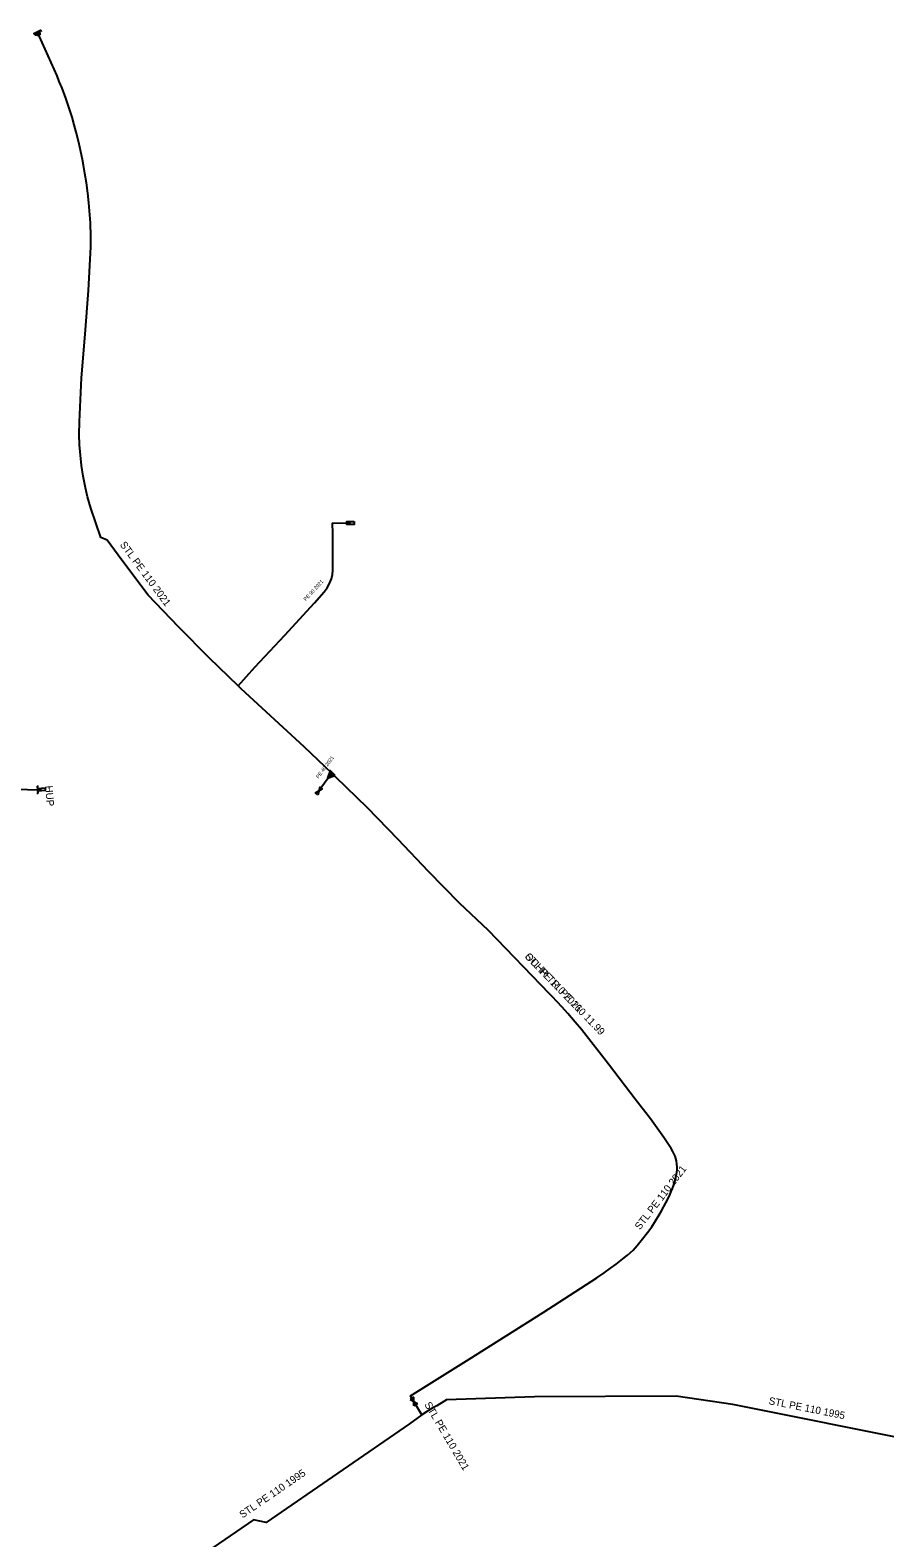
# Model space of a CAD drawing. Extents: x -734239 to -733693, y -1053757 to -1053379.
# Drawn here: x -734046.3 to -733929.8, y -1053596.5 to -1053391 of the extents above; entities that cross this region are included whole.
import ezdxf

# ---------------------------------------------------------------- set-up
doc = ezdxf.new("R2010")
doc.units = 0
for name, color, linetype in [('ST OP Chráni_ka - provoz', 7, 'Continuous'), ('ST Úsek p_ípojky - provoz', 7, 'Continuous'), ('ST Úsek plynovodu - provoz', 7, 'Continuous'), ('ST_HUP_22_23_popis', 7, 'Continuous'), ('Vrstva 1', 7, 'Continuous')]:
    doc.layers.add(name, color=color, linetype=linetype)

msp = doc.modelspace()

# ---------------------------------------------------------------- linework, layer by layer
at = {"layer": 'ST OP Chráni_ka - provoz'}
msp.add_lwpolyline([(-733975.51, -1053522.36), (-733983.84, -1053513.74)], dxfattribs=at)
at = {"layer": 'ST Úsek p_ípojky - provoz'}
for points in [[(-734017.98, -1053480.39), (-734015.69, -1053477.85), (-734011.61, -1053473.47), (-734007.56, -1053469.04), (-734006.24, -1053467.55), (-734005.83, -1053467.01), (-734005.5, -1053466.42), (-734005.26, -1053465.8), (-734005.11, -1053465.21), (-734005.04, -1053464.62), (-734005.04, -1053463.86), (-734005.08, -1053459.55), (-734005.09, -1053458.19), (-734002.93, -1053458.17), (-734002.65, -1053458.17)], [(-734005.43, -1053492.61), (-734006.98, -1053494.7)], [(-734005.16, -1053492.33), (-734005.43, -1053492.61)], [(-734056.77, -1053494.13), (-734056.37, -1053494.18), (-734045.32, -1053494.56)], [(-734045.32, -1053494.56), (-734044.78, -1053494.52)]]:
    msp.add_lwpolyline(points, dxfattribs=at)
at = {"layer": 'ST Úsek plynovodu - provoz'}
for points in [[(-733983.84, -1053513.74), (-733987.8, -1053509.99), (-733992, -1053505.69), (-733996.14, -1053501.33), (-734000.34, -1053497.03), (-734004.64, -1053492.85), (-734005.16, -1053492.33), (-734008.96, -1053488.69), (-734017.57, -1053480.78), (-734017.98, -1053480.39), (-734021.89, -1053476.62), (-734026.08, -1053472.34), (-734030.24, -1053468.01), (-734033.85, -1053463.23), (-734035.84, -1053460.54), (-734036.7, -1053460.16), (-734038.05, -1053456.17), (-734038.49, -1053454.59), (-734038.78, -1053453.4), (-734039.09, -1053451.81), (-734039.32, -1053450.33), (-734039.48, -1053448.95), (-734039.58, -1053447.5), (-734039.63, -1053446.1), (-734039.62, -1053444.37), (-734039.32, -1053438.39), (-734038.84, -1053432.43), (-734038.39, -1053426.48), (-734038.05, -1053420.51), (-734038.06, -1053419.11), (-734038.12, -1053417.26), (-734038.22, -1053415.61), (-734038.32, -1053414.52), (-734038.46, -1053413.22), (-734038.65, -1053411.82), (-734038.85, -1053410.54), (-734039.06, -1053409.41), (-734039.21, -1053408.63), (-734039.41, -1053407.59), (-734039.69, -1053406.31), (-734040.05, -1053404.87), (-734040.32, -1053403.88), (-734040.62, -1053402.83), (-734040.96, -1053401.76), (-734041.47, -1053400.24), (-734041.98, -1053398.88), (-734042.35, -1053397.97), (-734042.66, -1053397.22), (-734045.1, -1053391.76), (-734045.24, -1053391.46), (-734045.37, -1053391.2)], [(-733975.51, -1053522.36), (-733983.84, -1053513.74)], [(-733994.02, -1053577.94), (-733994.48, -1053577.19), (-733986.47, -1053572.19), (-733976.38, -1053565.81), (-733969.07, -1053561.09), (-733968.07, -1053560.42), (-733967.19, -1053559.79), (-733966.44, -1053559.23), (-733965.54, -1053558.52), (-733964.89, -1053557.98), (-733964.12, -1053557.31), (-733963.55, -1053556.67), (-733962.82, -1053555.79), (-733962.14, -1053554.9), (-733961.58, -1053554.12), (-733961.05, -1053553.31), (-733960.55, -1053552.51), (-733960.24, -1053551.97), (-733959.65, -1053550.87), (-733959.15, -1053549.93), (-733958.91, -1053549.34), (-733958.75, -1053548.92), (-733958.58, -1053548.41), (-733958.36, -1053547.64), (-733958.24, -1053547.15), (-733958.15, -1053546.7), (-733958.12, -1053546.37), (-733958.12, -1053545.99), (-733958.15, -1053545.58), (-733958.21, -1053545.16), (-733958.29, -1053544.84), (-733958.39, -1053544.52), (-733958.5, -1053544.24), (-733958.68, -1053543.86), (-733958.92, -1053543.46), (-733959.95, -1053541.94), (-733961.76, -1053539.4), (-733963.84, -1053536.74), (-733967.48, -1053531.98), (-733971.17, -1053527.25), (-733972.01, -1053526.22), (-733973, -1053525.06), (-733973.79, -1053524.18), (-733975.15, -1053522.75), (-733975.51, -1053522.36)], [(-733992.91, -1053579.78), (-733993.08, -1053579.54), (-733994.02, -1053577.94)], [(-733902.26, -1053596.38), (-733909.04, -1053590.79), (-733916.55, -1053586.18), (-733924.88, -1053583.48), (-733950.53, -1053578.36), (-733958.24, -1053577.23), (-733977.56, -1053577.32), (-733989.55, -1053577.74), (-733990.87, -1053578.54), (-733991.41, -1053578.81), (-733992.01, -1053579.18), (-733992.91, -1053579.78)], [(-733992.91, -1053579.78), (-733994.62, -1053581), (-734014.15, -1053594.44), (-734015.86, -1053594.09), (-734040.47, -1053610.96)]]:
    msp.add_lwpolyline(points, dxfattribs=at)
at = {"layer": 'Vrstva 1'}
for p, q in [((-734045.69, -1053391.68), (-734045.24, -1053391.46)), ((-734045.36, -1053494.06), (-734045.21, -1053494.05)), ((-734045.36, -1053494.06), (-734045.28, -1053495.06)), ((-734045.28, -1053495.06), (-734045.43, -1053495.07)), ((-733994.02, -1053577.36), (-733994.53, -1053577.67)), ((-733994.53, -1053577.67), (-733993.51, -1053578.22)), ((-733994.02, -1053578.53), (-733994.02, -1053577.36)), ((-733993.51, -1053578.22), (-733994.02, -1053578.53))]:
    msp.add_line(p, q, dxfattribs=at)
for points in [[(-734045.71, -1053391.64), (-734045.82, -1053391.42), (-734044.92, -1053390.98), (-734044.81, -1053391.21)], [(-734007.12, -1053495.22), (-734007.44, -1053494.98), (-734006.52, -1053494.42), (-734006.84, -1053494.18), (-734007.12, -1053495.22)]]:
    msp.add_lwpolyline(points, dxfattribs=at)
for points in [[(-734045.46, -1053391.58), (-734045.47, -1053391.56), (-734045.48, -1053391.54), (-734045.49, -1053391.51), (-734045.49, -1053391.49), (-734045.49, -1053391.46), (-734045.49, -1053391.44), (-734045.49, -1053391.41), (-734045.48, -1053391.39), (-734045.47, -1053391.37), (-734045.46, -1053391.35), (-734045.45, -1053391.32), (-734045.44, -1053391.3), (-734045.42, -1053391.29), (-734045.4, -1053391.27), (-734045.38, -1053391.26), (-734045.36, -1053391.24), (-734045.34, -1053391.23), (-734045.32, -1053391.22), (-734045.29, -1053391.22), (-734045.27, -1053391.21), (-734045.24, -1053391.21), (-734045.22, -1053391.21), (-734045.2, -1053391.22), (-734045.17, -1053391.22), (-734045.15, -1053391.23), (-734045.13, -1053391.24), (-734045.1, -1053391.25), (-734045.09, -1053391.27), (-734045.07, -1053391.28), (-734045.05, -1053391.3), (-734045.04, -1053391.32), (-734045.02, -1053391.34), (-734045.01, -1053391.36), (-734045, -1053391.39), (-734045, -1053391.41), (-734044.99, -1053391.44), (-734044.99, -1053391.46), (-734044.99, -1053391.49), (-734045, -1053391.51), (-734045, -1053391.53), (-734045.01, -1053391.56), (-734045.02, -1053391.58), (-734045.03, -1053391.6), (-734045.05, -1053391.62), (-734045.06, -1053391.64), (-734045.08, -1053391.65), (-734045.1, -1053391.67), (-734045.12, -1053391.68), (-734045.15, -1053391.69), (-734045.17, -1053391.7), (-734045.19, -1053391.71), (-734045.22, -1053391.71), (-734045.24, -1053391.71), (-734045.27, -1053391.71), (-734045.29, -1053391.71), (-734045.31, -1053391.7), (-734045.34, -1053391.69), (-734045.36, -1053391.68), (-734045.38, -1053391.67), (-734045.4, -1053391.66), (-734045.42, -1053391.64), (-734045.44, -1053391.62), (-734045.45, -1053391.6)], [(-734045.16, -1053391.62), (-734045.17, -1053391.62), (-734045.19, -1053391.63), (-734045.21, -1053391.63), (-734045.22, -1053391.64), (-734045.24, -1053391.64), (-734045.26, -1053391.64), (-734045.28, -1053391.63), (-734045.29, -1053391.63), (-734045.31, -1053391.62), (-734045.32, -1053391.62), (-734045.34, -1053391.61), (-734045.35, -1053391.6), (-734045.37, -1053391.59), (-734045.38, -1053391.57), (-734045.39, -1053391.56), (-734045.4, -1053391.55), (-734045.4, -1053391.53), (-734045.41, -1053391.51), (-734045.41, -1053391.5), (-734045.42, -1053391.48), (-734045.42, -1053391.46), (-734045.42, -1053391.45), (-734045.42, -1053391.43), (-734045.41, -1053391.41), (-734045.4, -1053391.4), (-734045.4, -1053391.38), (-734045.39, -1053391.37), (-734045.38, -1053391.35), (-734045.37, -1053391.34), (-734045.35, -1053391.33), (-734045.34, -1053391.32), (-734045.33, -1053391.31), (-734045.31, -1053391.3), (-734045.29, -1053391.29), (-734045.28, -1053391.29), (-734045.26, -1053391.29), (-734045.24, -1053391.29), (-734045.23, -1053391.29), (-734045.21, -1053391.29), (-734045.19, -1053391.29), (-734045.18, -1053391.3), (-734045.16, -1053391.31), (-734045.15, -1053391.32), (-734045.13, -1053391.33), (-734045.12, -1053391.34), (-734045.11, -1053391.35), (-734045.1, -1053391.36), (-734045.09, -1053391.38), (-734045.08, -1053391.39), (-734045.08, -1053391.41), (-734045.07, -1053391.43), (-734045.07, -1053391.44), (-734045.07, -1053391.46), (-734045.07, -1053391.48), (-734045.07, -1053391.5), (-734045.07, -1053391.51), (-734045.08, -1053391.53), (-734045.09, -1053391.54), (-734045.1, -1053391.56), (-734045.11, -1053391.57), (-734045.12, -1053391.59), (-734045.13, -1053391.6), (-734045.14, -1053391.61)], [(-734045.31, -1053391.33), (-734045.3, -1053391.32), (-734045.29, -1053391.32), (-734045.27, -1053391.31), (-734045.26, -1053391.31), (-734045.24, -1053391.31), (-734045.23, -1053391.31), (-734045.21, -1053391.31), (-734045.2, -1053391.32), (-734045.19, -1053391.32), (-734045.17, -1053391.33), (-734045.16, -1053391.34), (-734045.15, -1053391.35), (-734045.14, -1053391.36), (-734045.13, -1053391.37), (-734045.12, -1053391.38), (-734045.11, -1053391.39), (-734045.1, -1053391.4), (-734045.1, -1053391.42), (-734045.1, -1053391.43), (-734045.09, -1053391.45), (-734045.09, -1053391.46), (-734045.09, -1053391.48), (-734045.09, -1053391.49), (-734045.1, -1053391.51), (-734045.1, -1053391.52), (-734045.11, -1053391.53), (-734045.12, -1053391.55), (-734045.13, -1053391.56), (-734045.14, -1053391.57), (-734045.15, -1053391.58), (-734045.16, -1053391.59), (-734045.17, -1053391.59), (-734045.18, -1053391.6), (-734045.2, -1053391.61), (-734045.21, -1053391.61), (-734045.23, -1053391.61), (-734045.24, -1053391.61), (-734045.26, -1053391.61), (-734045.27, -1053391.61), (-734045.29, -1053391.61), (-734045.3, -1053391.6), (-734045.31, -1053391.6), (-734045.33, -1053391.59), (-734045.34, -1053391.58), (-734045.35, -1053391.57), (-734045.36, -1053391.56), (-734045.37, -1053391.55), (-734045.37, -1053391.53), (-734045.38, -1053391.52), (-734045.39, -1053391.51), (-734045.39, -1053391.49), (-734045.39, -1053391.48), (-734045.39, -1053391.46), (-734045.39, -1053391.45), (-734045.39, -1053391.43), (-734045.39, -1053391.42), (-734045.38, -1053391.41), (-734045.38, -1053391.39), (-734045.37, -1053391.38), (-734045.36, -1053391.37), (-734045.35, -1053391.36), (-734045.34, -1053391.35), (-734045.33, -1053391.34)], [(-734045.28, -1053391.4), (-734045.27, -1053391.39), (-734045.27, -1053391.39), (-734045.26, -1053391.39), (-734045.25, -1053391.39), (-734045.24, -1053391.39), (-734045.24, -1053391.39), (-734045.23, -1053391.39), (-734045.22, -1053391.39), (-734045.21, -1053391.39), (-734045.21, -1053391.4), (-734045.2, -1053391.4), (-734045.2, -1053391.4), (-734045.19, -1053391.41), (-734045.18, -1053391.41), (-734045.18, -1053391.42), (-734045.18, -1053391.43), (-734045.17, -1053391.43), (-734045.17, -1053391.44), (-734045.17, -1053391.45), (-734045.17, -1053391.45), (-734045.17, -1053391.46), (-734045.17, -1053391.47), (-734045.17, -1053391.48), (-734045.17, -1053391.48), (-734045.17, -1053391.49), (-734045.18, -1053391.5), (-734045.18, -1053391.5), (-734045.18, -1053391.51), (-734045.19, -1053391.52), (-734045.2, -1053391.52), (-734045.2, -1053391.52), (-734045.21, -1053391.53), (-734045.21, -1053391.53), (-734045.22, -1053391.53), (-734045.23, -1053391.54), (-734045.23, -1053391.54), (-734045.24, -1053391.54), (-734045.25, -1053391.54), (-734045.26, -1053391.54), (-734045.26, -1053391.53), (-734045.27, -1053391.53), (-734045.28, -1053391.53), (-734045.28, -1053391.52), (-734045.29, -1053391.52), (-734045.3, -1053391.52), (-734045.3, -1053391.51), (-734045.3, -1053391.5), (-734045.31, -1053391.5), (-734045.31, -1053391.49), (-734045.31, -1053391.48), (-734045.32, -1053391.48), (-734045.32, -1053391.47), (-734045.32, -1053391.46), (-734045.32, -1053391.46), (-734045.32, -1053391.45), (-734045.31, -1053391.44), (-734045.31, -1053391.43), (-734045.31, -1053391.43), (-734045.3, -1053391.42), (-734045.3, -1053391.41), (-734045.3, -1053391.41), (-734045.29, -1053391.4), (-734045.28, -1053391.4)], [(-734002.15, -1053457.97), (-734002.15, -1053458.37), (-734003.15, -1053458.37), (-734003.15, -1053457.97)], [(-734004.72, -1053492.59), (-734005.44, -1053491.9), (-734005.77, -1053492.97)], [(-734005.39, -1053492.08), (-734005.62, -1053492.81), (-734004.9, -1053492.55)], [(-734005.46, -1053492.65), (-734005.09, -1053492.51), (-734005.35, -1053492.27)], [(-734044.3, -1053494.27), (-734044.27, -1053494.67), (-734045.27, -1053494.76), (-734045.3, -1053494.36)]]:
    msp.add_lwpolyline(points, close=True, dxfattribs=at)

# ---------------------------------------------------------------- texts
at = {"layer": 'ST OP Chráni_ka - provoz'}
msp.add_text('OCHR.TR. PE 160 11.99', height=1, rotation=314.0198, dxfattribs=at).set_placement((-733978.96, -1053517.36))
at = {"layer": 'ST Úsek p_ípojky - provoz'}
for s, rotation, p in [('PE 90 2021', 47.5658, (-734008.74, -1053468.85)), ('PE 40 2021', 53.3894, (-734007.01, -1053493.06))]:
    msp.add_text(s, height=0.5, rotation=rotation, dxfattribs=at).set_placement(p)
at = {"layer": 'ST Úsek plynovodu - provoz'}
for s, rotation, p in [('STL PE 110 2021', 306.4932, (-734034.15, -1053461.14)), ('STL PE 110 2021', 314.0198, (-733978.96, -1053517.36)), ('STL PE 110 2021', 52.5442, (-733963.19, -1053554.63)), ('STL PE 110 2021', 300.5126, (-733992.61, -1053578.36)), ('STL PE 110 1995', 348.7115, (-733945.69, -1053578.31)), ('STL PE 110 1995', 34.4298, (-734017.37, -1053593.91))]:
    msp.add_text(s, height=1, rotation=rotation, dxfattribs=at).set_placement(p)
at = {"layer": 'ST_HUP_22_23_popis'}
msp.add_text('HUP', height=1, rotation=274.71, dxfattribs=at).set_placement((-734044.28, -1053494.02))

doc.saveas('drawing.dxf')
